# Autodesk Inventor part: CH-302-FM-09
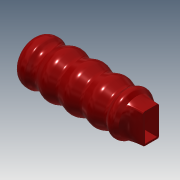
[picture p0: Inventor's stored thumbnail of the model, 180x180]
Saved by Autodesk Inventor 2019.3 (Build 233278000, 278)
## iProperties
Created: 2013-03
Part Number: CH-302-FM-09
Material: Ogólny
Document SubType Name: Modeling
Designer: CADENGINEERING4
Density: 1 g/cm^3
Appearance: Czerwona
Author: CADENGINEERING4
Revision Number: ÈÎºÎ
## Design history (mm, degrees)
feature "Ô²½Ç11"
node "Bryła1"
